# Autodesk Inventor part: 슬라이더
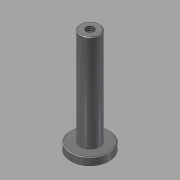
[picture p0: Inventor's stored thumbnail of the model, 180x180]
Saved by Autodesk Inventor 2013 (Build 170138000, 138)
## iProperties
Created: 2016-02
Part Number: 슬라이더
Material: 스테인리스강
Document SubType Name: Modeling
Designer: mduedu
Density: 8.08 g/cm^3
Author: mduedu
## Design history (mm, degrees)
sketch "스케치1"
  geometry: C1 r 12 at (0, 0); 1 further point
  constraints: 1 centre point, 1 coincident
  dimensions: "d0" = 24 diameter of C1
extrude "돌출1" new body sketch "스케치1" distance "d1" = 5; taper "d2" = 0 deg
sketch "스케치2"
  geometry: C1 r 6 at (0, 0); 1 further point
  constraints: 1 centre point, 1 coincident
  dimensions: "d3" = 12 diameter of C1
extrude "돌출2" join sketch "스케치2" distance "d4" = 60; taper "d5" = 0 deg
chamfer "모따기1" distance "d6" = 0.5; stored, may be unused: second distance "d7" = 2, angle "d8" = 45 deg
hole "구멍1" diameter "d11" = 4.917; stored, may be unused: countersink angle "d15" = 90 deg, drill point angle "d17" = 118 deg; dims "d9" = 10, "d10" = 10, "d12" = 10, "d13" = 4, "d14" = 2, "d16" = 12
chamfer "모따기2" distance "d18" = 0.5; stored, may be unused: second distance "d19" = 2, angle "d20" = 45 deg
node "솔리드1"
